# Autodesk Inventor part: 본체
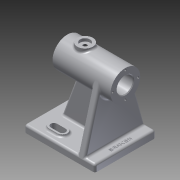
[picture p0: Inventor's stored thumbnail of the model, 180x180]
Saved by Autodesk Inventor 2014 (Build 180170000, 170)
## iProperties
Created: 2019-10
Part Number: 본체
Material: Aluminum 6061
Document SubType Name: Modeling
Designer: kh
Density: 2.71 g/cm^3
Appearance: Aluminum - Flat
Mass: 588.435 g
Surface Area: 540.74 cm^2
Volume: 217.135 cm^3
Author: kh
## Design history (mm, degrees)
sketch "Sketch1"
  geometry: L1 (-50, -43)-(50, -43); L2 (50, -43)-(50, 43); L3 (50, 43)-(-50, 43); L4 (-50, 43)-(-50, -43); L5 (-50, -43)-(50, 43); L6 (50, -43)-(-50, 43); 1 further point
  constraints: 12 end point, 2 midpoint, 2 parallel, 1 horizontal, 1 perpendicular
  dimensions: "d0" = 100 distance of L3.end L2.end; "d1" = 86 distance of L1.end L2.end
extrude "Extrusion1" new body sketch "Sketch1" distance "d2" = 10; taper "d3" = 0 deg
sketch "Sketch2"
  geometry: L1 (-50, 0)-(50, 0) reference; L2 (-50, 0)-(-50, 86); L3 (-50, 86)-(32, 86); L4 (32, 86)-(32, 107); L5 (32, 107)-(-50, 107); L6 (-50, 107)-(-50, 86); L7 (32, 100.5)-(-30, 100.5); L8 (-30, 100.5)-(-30, 97.5); L9 (-30, 97.5)-(-50, 97.5); 1 further point
  constraints: 16 end point, 7 perpendicular, 2 point on line, 1 parallel
  dimensions: "d4" = 86 distance of L1.start L2.end; "d5" = 82 distance of L2.end L3.end; "d6" = 42 diameter of L5 L3; "d7" = 62 distance between parallel lines of L4 L8; "d8" = 23 diameter of L9 L3; "d9" = 29 diameter of L7 L3
revolve "Revolution1" sketch "Sketch2" stored, may be unused: angle "d10" = 90 deg
chamfer "Chamfer1" distance "d11" = 1; stored, may be unused: second distance "d12" = 2, angle "d13" = 45 deg
workplane "Work Plane1"
sketch "Sketch3"
  geometry: L1 (-32, 21)-(-32, -21) reference; L2 (-32, 0)-(-7, 0); C1 r 11 at (-7, 0); 1 further point
  constraints: 2 end point, 1 centre point, 1 coincident, 1 midpoint, 1 perpendicular
  dimensions: "d15" = 25 distance of L2.start L2.end; "d16" = 22 diameter of C1
extrude "Extrusion2" join sketch "Sketch3" stored distance "d17" = 10; taper "d18" = 0 deg
hole "Hole1" diameter "d21" = 5.242; stored, may be unused: countersink angle "d25" = 90 deg, drill point angle "d27" = 118 deg; dims "d22" = 6, "d23" = 14, "d24" = 4, "d26" = 8, "d85" = 10, "d86" = 10
workplane "Work Plane2"
sketch "Sketch5"
  geometry: L1 (-50, -43)-(50, -43) reference; L2 (50, -43)-(50, 43) reference; L3 (50, 43)-(-50, 43) reference; L4 (-50, 43)-(-50, -43) reference; L5 (50, 0)-(-50, 0); L6 (-24, 27)-(-12, 27); L7 (-24, 20)-(-12, 20); L8 (-12, 34)-(-24, 34); L9 (-24, 27)-(-12, 27); L10 (-24, 22.5)-(-12, 22.5); L11 (-12, 31.5)-(-24, 31.5); A1 r 7 centre (-24, 27) between (-24, 34) and (-24, 20); A2 r 7 centre (-12, 27) between (-12, 20) and (-12, 34); A3 r 4.5 centre (-24, 27) between (-24, 31.5) and (-24, 22.5); A4 r 4.5 centre (-12, 27) between (-12, 22.5) and (-12, 31.5); 3 further points
  constraints: 18 end point, 8 point on circle, 8 tangent, 4 centre point, 4 midpoint, 4 parallel, 1 coincident
  dimensions: "d31" = 14 diameter of A2; "d32" = 12 distance of L6.end L6.start; "d33" = 27 distance from line of L5 point (-18, 27); "d35" = 12 distance of L9.start L9.end; "d36" = 9 diameter of A4; "d84" = 26 horizontal distance of L3.end L9.start
  node "Projected Loop2"
extrude "Extrusion3" join sketch "Sketch5" stored distance "d37" = 10; taper "d38" = 0 deg
extrude "Extrusion4" cut sketch "Sketch5" stored distance "d39" = 10; taper "d40" = 0 deg
mirror "Mirror1"
workplane "Work Plane3"
fillet "Fillet1" dims "d44" = 3
fillet "Fillet2" dims "d45" = 3
sketch "Sketch7"
  geometry: L1 (-10, 3)-(-10, 83) reference; L2 (-7, 86)-(0, 86) reference; L3 (0, 86)-(0, 0) reference; L4 (0, 0)-(-7, 0) reference; L5 (-10, 3)-(-10, 83) reference; L6 (-7, 86)-(0, 86) reference; L7 (0, 86)-(0, 0) reference; L8 (0, 0)-(-7, 0) reference; L9 (-7.783, 0.104)-(-91.48, 22.728); L10 (-7.783, 85.896)-(-91.48, 63.272); L11 (-10, 3)-(-10, 83); C1 r 11.5 at (-86, 43) reference; C2 r 11.5 at (-86, 43) reference; A1 r 3 centre (-7, 83) between (-7, 86) and (-10, 83) reference; A2 r 3 centre (-7, 3) between (-10, 3) and (-7, 0) reference; A3 r 21 centre (-86, 43) between (-91.48, 22.728) and (-91.48, 63.272) reference; A4 r 3 centre (-7, 83) between (-7, 86) and (-10, 83) reference; A5 r 3 centre (-7, 3) between (-10, 3) and (-7, 0) reference; A6 r 21 centre (-86, 43) between (-91.48, 22.728) and (-91.48, 63.272) reference; A7 r 3 centre (-7, 3) between (-10, 3) and (-7.783, 0.104); A8 r 3 centre (-7, 83) between (-7.783, 85.896) and (-10, 83); A9 r 21 centre (-86, 43) between (-91.48, 22.728) and (-91.48, 63.272); 1 further point
  constraints: 14 point on circle, 10 tangent, 6 end point, 3 centre point, 3 coincident, 1 collinear
extrude "Extrusion6" join sketch "Sketch7" distance "d46" = 10; taper "d47" = 0 deg
sketch "Sketch8"
  geometry: L1 (47, 10)-(-25, 10) reference; L2 (50, 0)-(50, 7) reference; L3 (35, 10)-(22.683, 43.842); 1 further point
  constraints: 2 end point, 1 point on line
  dimensions: "d48" = 15 horizontal distance of L3.start L2.end; "d49" = 70 deg angle of L3 L1
feature "Rib1" sketch "Sketch8" dims "d50" = 1, "d51" = 10, "d52" = 0, "d53" = 0, "d54" = 1, "d55" = 1
fillet "Fillet3" dims "d56" = 3
fillet "Fillet4" dims "d57" = 3
sketch "Sketch9"
  geometry: L1 (37.641, -24.675)-(37.641, 24.675); L2 (37.641, 24.675)-(48.359, 24.675); L3 (48.359, 24.675)-(48.359, -24.675); L4 (48.359, -24.675)-(37.641, -24.675); L5 (37.641, -24.675)-(48.359, 24.675); L6 (37.641, 24.675)-(48.359, -24.675); L7 (-47, -43)-(47, -43) reference; L8 (50, -40)-(50, 40) reference; 2 further points
  constraints: 4 end point, 1 midpoint, 2 other
  dimensions: "d58" = 43 distance from line of point (43, 0) L7; "d59" = 7 distance from line of point (43, 0) L8
emboss "Emboss1" sketch "Sketch9" dims "d0" = 100, "d1" = 86, "d60" = 0.5, "d61" = 0
sketch "Sketch10"
  geometry: L1 (0, 0)-(-18, 0); C1 r 21 at (0, 0) reference; 2 further points
  constraints: 2 end point, 1 coincident, 1 horizontal
  dimensions: "d62" = 18 distance of L1.start L1.end
hole "Hole2" sketch "Sketch10" at (-18, 0) diameter "d63" = 2.621; stored, may be unused: countersink angle "d67" = 90 deg, drill point angle "d69" = 118 deg; dims "d64" = 8, "d65" = 14, "d66" = 4, "d68" = 10
pattern_circular "Circular Pattern1" dims angle "d71" = 360 deg
sketch "Sketch11"
  geometry: L1 (0, 0)-(18, 0); C1 r 21 at (0, 0) reference; 2 further points
  constraints: 2 end point, 1 coincident, 1 horizontal
  dimensions: "d73" = 18 distance of L1.start L1.end
hole "Hole3" sketch "Sketch11" at (18, 0) diameter "d74" = 2.621; stored, may be unused: countersink angle "d78" = 90 deg, drill point angle "d80" = 118 deg; dims "d75" = 8, "d76" = 14, "d77" = 4, "d79" = 10
pattern_circular "Circular Pattern2" dims angle "d82" = 360 deg
body "Solid1"
node "Project Cut Edges1"
node "Project Cut Edges2"
other parameters: "d30" = -13, "d41" = -15
